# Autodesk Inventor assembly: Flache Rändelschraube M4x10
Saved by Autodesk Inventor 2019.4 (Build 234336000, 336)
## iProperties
Created: 2021-06
Part Number: Flache Rändelschraube M4x10
Document SubType Name: Assembly
Designer: Administrator
Title: Flache Rändelschraube M4x10 v2
Author: Administrator
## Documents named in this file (2)
- c:\worker\convert-fusion-r04\tmp\job-1\39\output\files\e1e84fd7-b652-4e3d-a1c7-f0a54bbc30a7\Flache Rändelschraube M4x10 v2.iam
- c:\worker\convert-fusion-r04\tmp\job-1\39\output\files\e1e84fd7-b652-4e3d-a1c7-f0a54bbc30a7\_Flat knurled screw DIN 653-M4-10-ZB.ipt
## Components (1 placed, 1 different names)
1. _Flat knurled screw DIN 653-M4-10-ZB:1
